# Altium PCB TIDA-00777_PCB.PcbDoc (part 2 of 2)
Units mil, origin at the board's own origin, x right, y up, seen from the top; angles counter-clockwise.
Board outline 1968.5 x 2165.35 mil, 4 copper layers (Top Layer, GND, +2.5V, Bottom Layer), stack 30.48 mil thick; 147 components, 52 nets, 290 pads, 85 vias.
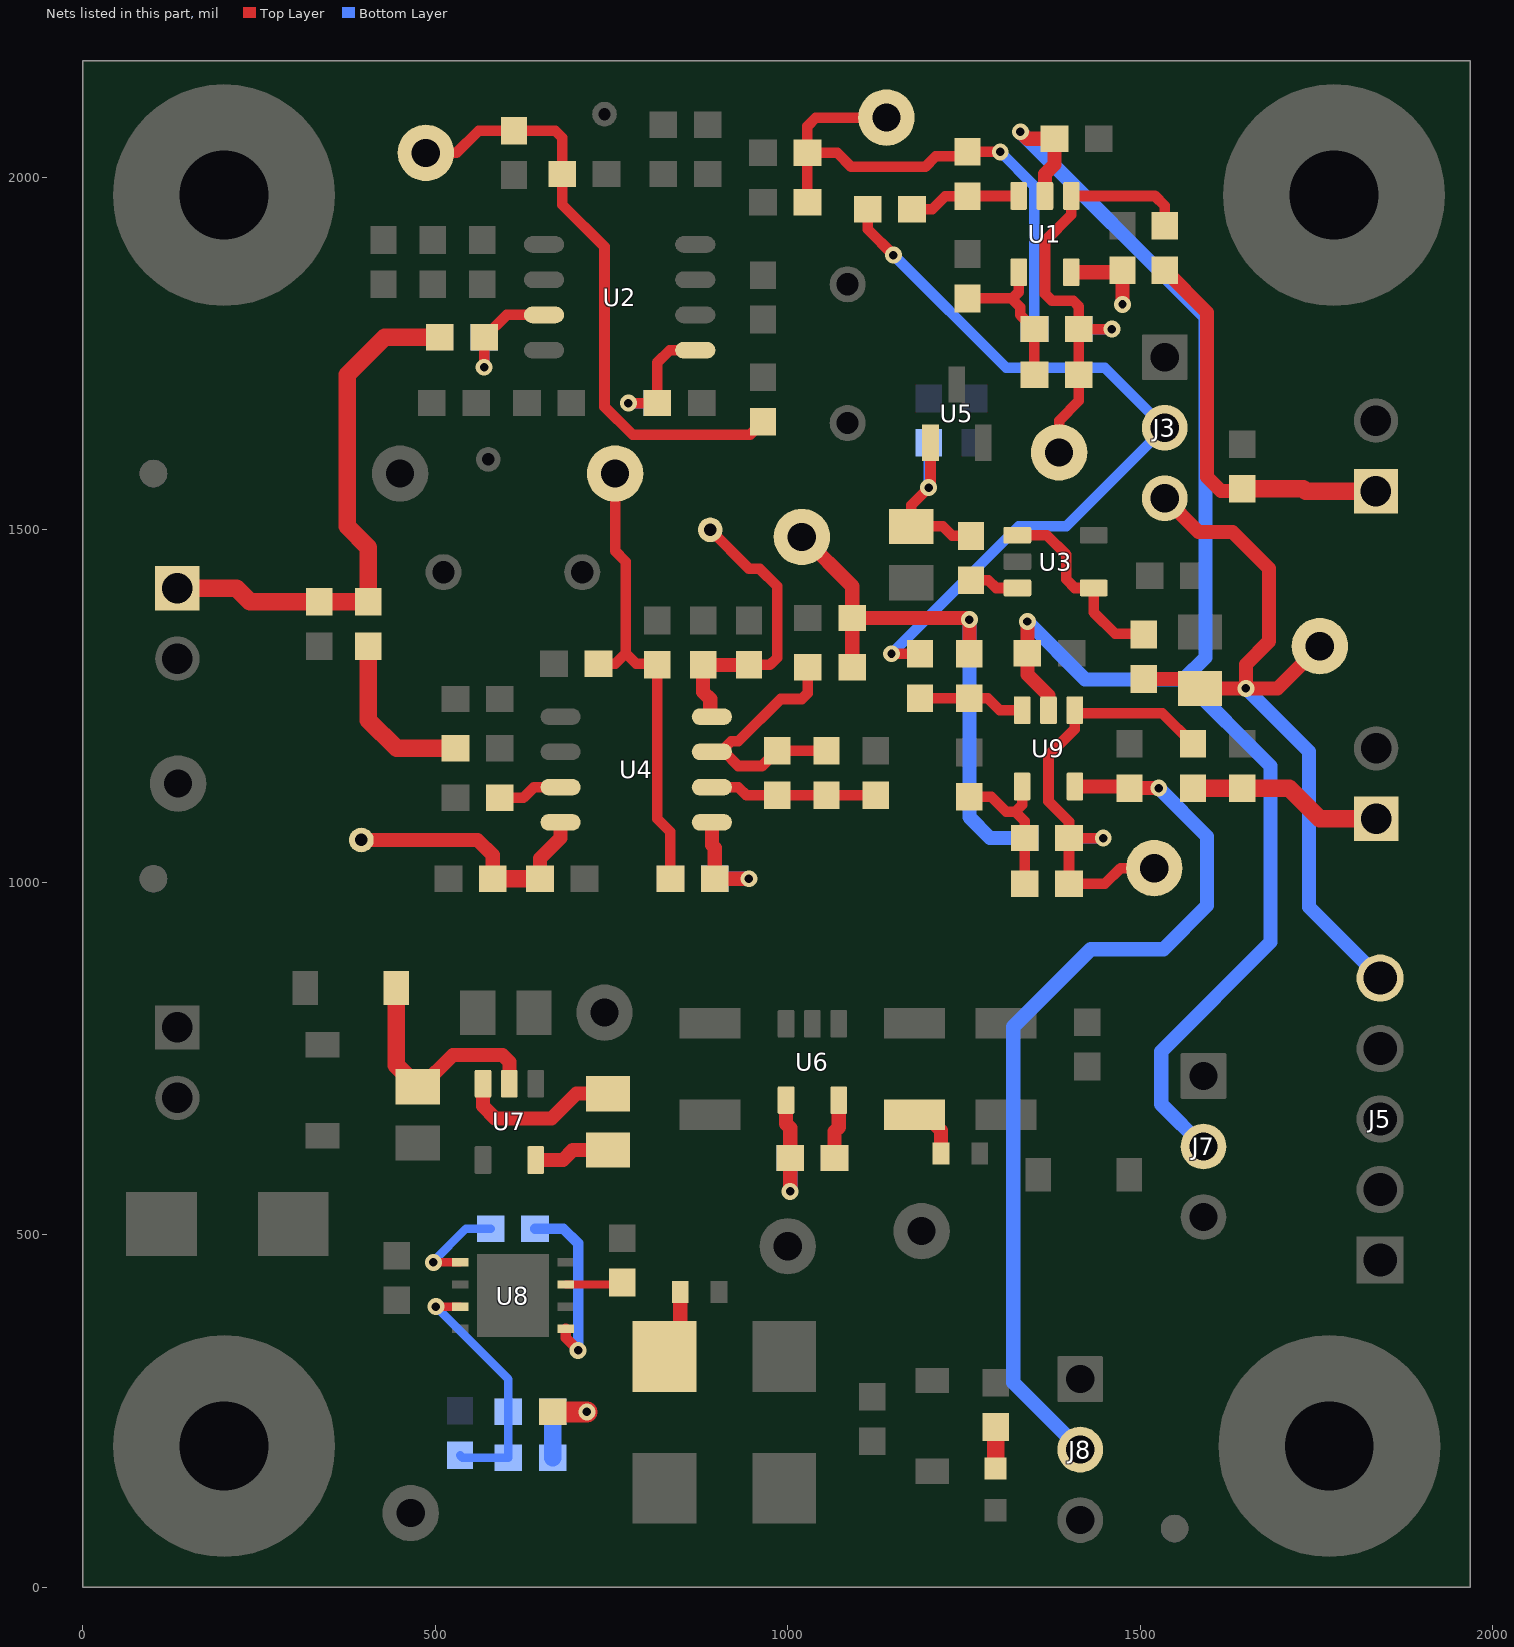
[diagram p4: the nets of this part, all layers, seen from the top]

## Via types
v1: diameter 24, hole 12, Top Layer to Bottom Layer, tented both sides, 79 vias
v2: diameter 19.68, hole 7.87, Top Layer to Bottom Layer, 5 vias
v3: diameter 40, hole 20, Top Layer to Bottom Layer, tented both sides, 1 vias

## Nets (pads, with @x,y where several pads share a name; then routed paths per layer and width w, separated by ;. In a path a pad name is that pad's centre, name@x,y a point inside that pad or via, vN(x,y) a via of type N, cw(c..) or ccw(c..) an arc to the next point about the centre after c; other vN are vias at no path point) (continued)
NetC13_2: C13.2 R47.2 TP17.1 U4.8 | length 433.9
  Top Layer w15: TP17.1@890,1500 945,1445 960,1445 985,1420 985,1318.73 974.77,1308.5 R47.2@945,1308.5
  Top Layer w20: U4.8@909,1235 U4.8@892.28,1235 890,1237.28 890,1260 880,1270 C13.2@880,1308.5 R47.2@945,1308.5
NetC14_1: C14.1 R20.1 R25.2 U4.6 | length 237.5
  Top Layer w15: U4.6@892.28,1135 930,1135 941.5,1123.5 R20.1@985,1123.5 C14.1@1055,1123.5 R25.2@1125,1123.5
NetC14_2: C14.2 R20.2 R54.1 U4.7 | length 374.5
  Top Layer w15: U4.7@892.28,1185 U4.7@905,1185 ; R54.1@1028.5,1305 1028.5,1268.5 1020,1260 990,1260 930,1200 920,1200 U4.7@905,1185 ; C14.2@1055,1186.5 R20.2@985,1186.5 963.5,1165 930,1165 910,1185 U4.7@905,1185
NetC15_1: C15.1 R22.1 R36.2 U5.1 | length 284.2
  Top Layer w15: U5.1@1202.6,1623.66 1202.6,1562.6 v1(1200,1560) 1175,1535 C15.1@1175,1505 1220,1505 1233.5,1491.5 R22.1@1260,1491.5
  Bottom Layer w15: v1(1200,1560) R36.2@1200,1623.5
NetC16_2: C16.2 R53.2 TP18.1 U4.4 | length 388
  Top Layer w20: TP18.1@395,1060 560,1060 581.5,1038.5 R53.2@581.5,1005 ; C16.2@648.5,1005 648.5,1033.5 677.72,1062.72 U4.4@677.72,1085
  Top Layer w25: R53.2@581.5,1005 C16.2@648.5,1005
NetC20_1: C20.1 L1.1 R29.2 U6.5 | length 173.9
  Top Layer w20: R29.2@1066.5,608.7 1066.5,646.5 1072.4,652.4 U6.5@1072.4,690.87 ; C20.1@1189.96,670.04 C20.1@1180,670.04 1194.96,670.04 1217.44,647.56 L1.1@1217.44,615
NetC22_1: C22.1 D3.1 U7.2 | length 336.3
  Top Layer w20: C22.1@475,710 480,710 525,755 595,755 605,745 U7.2@605,714.13
  Top Layer w25: D3.1@444.47,850 444.47,740.53 C22.1@475,710
NetC23_1: C23.1 U7.3 | length 230.8
  Top Layer w20: U7.3@567.6,714.13 567.6,682.4 585,665 665,665 700,700 C23.1@745,700
NetC23_2: C23.2 U7.5 | length 108.5
  Top Layer w20: U7.5@642.4,605.87 680.87,605.87 695,620 C23.2@745,620
NetC26_1: C26.1 C29.1 C31.1 L2.1 R39.2 R41.2 U8.1 | length 522.1
  Top Layer w15: U8.1@684.8,366.26 684.8,353.46 v1(702.52,335.75)
  Top Layer w20: C26.1@825,327.01 847.44,349.45 L2.1@847.44,418.5
  Top Layer w30: C29.1@666.5,248.5 v1(715,248.5)
  Bottom Layer w15: R39.2@641.5,508.5 681.5,508.5 702.52,487.48 v1(702.52,335.75)
  Bottom Layer w25: R41.2@666.5,183.5 C31.1@666.5,248.5 v1(715,248.5)
NetC31_2: C31.2 R40.2 R41.1 U8.7 | length 361.2
  Top Layer w12: v1(500.75,397.76) U8.7@535.2,397.76
  Bottom Layer w12: v1(500.75,397.76) 603.5,295 C31.2@603.5,248.5 R41.1@603.5,183.5 538.5,183.5 R40.2@535,187.01
NetC32_1: C32.1 R7.2 R12.1 U1.4 | length 226.3
  Top Layer w15: R7.2@1255,1828.5 1317.5,1828.5 ; U1.4@1327.6,1865.55 1327.6,1837.6 1318.5,1828.5 1317.5,1828.5 ; C32.1@1350,1720 R12.1@1350,1785 1330,1805 1330,1816 1317.5,1828.5
NetC32_2: C32.2 R12.2 R14.1 R33.2 TP3.1 U1.1 | length 689.2
  Top Layer w15: TP3.1@1385,1610 1385,1655 1412.99,1682.99 C32.2@1412.99,1720 R12.2@1412.99,1785 ; v1(1460,1785) R12.2@1412.99,1785 ; R14.1@1535,1931.5 1535,1960 1521.18,1973.82 U1.1@1402.4,1973.82 1402.4,1947.4 1365,1910 1365,1835 1375,1825 1405,1825 1412.99,1817.01 R12.2@1412.99,1785
  Bottom Layer w15: R33.2@1412.99,1785 v1(1460,1785)
NetC33_2: C33.2 J1.1 R14.2 | length 569.2
  Top Layer w20: R14.2@1535,1868.5 1595,1808.5 1595,1575 1615,1555 1641.5,1555 C33.2@1645,1558.5
  Top Layer w25: C33.2@1645,1558.5 1731.5,1558.5 1735,1555 J1.1@1834.65,1555
NetC34_1: C34.1 R45.2 R46.1 U9.4 | length 221.6
  Top Layer w15: R45.2@1257.64,1121.26 1288.74,1121.26 1310,1100 1322.6,1100 ; U9.4@1332.6,1135.87 1332.6,1110 1322.6,1100 ; C34.1@1336.14,997.76 R46.1@1336.14,1062.76 1336.14,1086.46 1322.6,1100
NetC34_2: C34.2 R26.1 R46.2 R49.2 TP14.1 U9.1 | length 709.8
  Top Layer w15: v1(1447.76,1062.76) R46.2@1399.13,1062.76 ; TP14.1@1520,1020 TP14.1@1505,1020 ; TP14.1@1520,1035 TP14.1@1505,1020 ; R26.1@1575,1196.5 1531.5,1240 1411.54,1240 U9.1@1407.4,1244.13 1407.4,1217.4 1370,1180 1370,1115 1399.13,1085.87 R46.2@1399.13,1062.76 ; R46.2@1399.13,1062.76 C34.2@1399.13,997.76 1450,997.76 1472.24,1020 TP14.1@1505,1020
  Bottom Layer w15: R49.2@1399.13,1062.82 1399.2,1062.76 v1(1447.76,1062.76)
NetC36_2: C36.2 J4.1 R26.2 | length 278
  Top Layer w25: R26.2@1575,1133.5 C36.2@1645,1133.5 1711.5,1133.5 1755,1090 J4.1@1835,1090
NetD5_1: D5.1 R31.1 | length 59
  Top Layer w25: D5.1@1295,168.03 R31.1@1295,227.01
NetJ2_1: J2.1 R9.1 R16.2 R17.2 | length 766.9
  Top Layer w25: J2.1@133.86,1417.24 217.76,1417.24 237.01,1397.99 R16.2@335,1397.99 R17.2@405,1397.99 405,1475 375,1505 375,1720 428.23,1773.23 R9.1@506.3,1773.23
NetR1_2: R1.2 R4.2 U1.3 | length 158.9
  Top Layer w15: R4.2@1176.5,1955 1205,1955 1223.5,1973.5 R1.2@1255,1973.5 1255.31,1973.82 U1.3@1327.6,1973.82
NetR9_2: R9.2 R32.2 U2.3 | length 182.9
  Top Layer w15: v1(569.29,1730.8) R9.2@569.29,1773.23 601.06,1805 U2.3@654.21,1805
  Bottom Layer w15: v1(569.29,1730.8) R32.2@569.29,1773.23
NetR13_2: R13.2 R34.1 U2.5 | length 200.5
  Top Layer w15: v1(774,1680) R13.2@815,1680 815,1737.5 832.5,1755 U2.5@868.78,1755
  Bottom Layer w15: v1(774,1680) R34.1@815,1680
NetR15_1: R15.1 U3.1 U3.4 | length 278.3
  Top Layer w15: U3.1@1325.87,1492.4 1367.6,1492.4 1395,1465 1395,1430 1407.4,1417.6 U3.4@1434.13,1417.6 1434.13,1382.87 1464.63,1352.37 1504.12,1352.37 R15.1@1505,1351.5
NetR17_1: R17.1 R21.1 | length 245.1
  Top Layer w25: R17.1@405,1335 405,1230 445,1190 R21.1@528.5,1190
NetR22_2: R22.2 U3.3 | length 70.4
  Top Layer w15: R22.2@1260,1428.5 1284.76,1428.5 1295.67,1417.6 U3.3@1325.87,1417.6
NetR24_2: R24.2 U4.3 | length 92.4
  Top Layer w15: R24.2@591.5,1120 625,1120 640,1135 U4.3@677.72,1135
NetR27_2: R27.2 R37.2 U4.5 | length 178.8
  Top Layer w20: U4.5@892.28,1085 892.28,1052.72 896.5,1048.5 R27.2@896.5,1005 v1(945,1005)
  Bottom Layer w20: R37.2@896.5,1005 v1(945,1005)
NetR29_1: R29.1 R38.2 U6.4 | length 179
  Top Layer w20: U6.4@997.6,690.87 997.6,657.4 1003.5,651.5 R29.1@1003.5,608.7 v1(1003.5,561.5)
  Bottom Layer w20: v1(1003.5,561.5) R38.2@1003.5,608.7
NetR30_2: R30.2 U8.3 | length 80.5
  Top Layer w12: U8.3@684.8,429.25 764.25,429.25 R30.2@765,428.5
NetR39_1: R39.1 U8.5 | length 139.9
  Top Layer w12: v1(497.24,460.75) U8.5@535.2,460.75
  Bottom Layer w12: v1(497.24,460.75) 497.24,462.24 543.5,508.5 R39.1@578.5,508.5
NetR50_2: R50.2 R51.2 U9.3 | length 152.1
  Top Layer w15: R51.2@1187.64,1261.26 R50.2@1257.64,1261.26 1283.74,1261.26 1300.87,1244.13 U9.3@1332.6,1244.13
REF_2.5V: C9.1 J3.3 J5.5 R15.2 TP4.1 | length 1143.4
  Top Layer w20: R15.2@1505,1288.5 1571.5,1288.5 C9.1@1585,1275 v1(1650,1275) ; J3.3@1535,1545 1583,1497 1631,1497 1683,1445 1683,1342 1650,1309 v1(1650,1275) ; TP4.1@1755,1335 1695,1275 v1(1650,1275)
  Bottom Layer w20: v1(1650,1275) 1739.61,1185.39 1739.61,965 J5.5@1840.55,864.06
V+: C5.2 C35.2 J8.2 U1.5 U9.5 | length 1427.9
  Top Layer w20: U1.5@1402.4,1865.55 C5.2@1475,1865.55 ; U9.5@1407.4,1135.87 1482.64,1135.87 C35.2@1485,1133.5 v1(1526.5,1133.5) ; v1(1475,1820) C5.2@1475,1865.55 ; C5.2@1475,1868.5 C5.2@1475,1865.55 ; C5.2@1480,1868.5 1477.05,1865.55 C5.2@1475,1865.55
  Bottom Layer w20: J8.2@1415,195 1320,290 1320,795 1430,905 1533,905 1595,967 1595,1065 v1(1526.5,1133.5)
V-: C3.2 C37.2 J7.2 U1.2 U9.2 | length 2235.5
  Top Layer w20: v1(1330,2065) 1340,2055 C3.2@1378.5,2055 1378.5,2018.5 1365,2005 U1.2@1365,1973.82 ; v1(1340,1370) C37.2@1340,1325 1340,1295 1370,1265 U9.2@1370,1244.13
  Bottom Layer w20: v1(1330,2065) 1593,1802 1593,1319 1562,1288 ; v1(1340,1370) 1422,1288 1562,1288 ; J7.2@1590,625 1530,685 1530,760 1685,915 1685,1165 1562,1288
V_REF: J3.2 R4.1 R51.1 | length 1127.6
  Top Layer w15: R4.1@1113.5,1955 1113.5,1926.5 v1(1150,1890) ; v1(1147.24,1324.25) R51.1@1187.64,1324.25
  Bottom Layer w15: v1(1147.24,1324.25) 1327.99,1505 1395,1505 J3.2@1535,1645 1450,1730 1310,1730 v1(1150,1890)
VM_GAIN: C4.1 R2.2 R11.1 TP2.1 | length 866.3
  Top Layer w15: TP2.1@486.5,2035 530,2035 561.5,2066.5 R2.2@611.5,2066.5 670,2066.5 680,2056.5 C4.1@680,2005 680,1961.5 740,1901.5 740,1675 780,1635 946.5,1635 R11.1@965,1653.5
VM_INTEGRATOR: C2.1 R1.1 R3.2 R33.1 TP1.1 | length 787.3
  Top Layer w15: R3.2@1027.99,1965 C2.1@1027.99,2035 ; TP1.1@1140,2085 1040,2085 1027.99,2072.99 C2.1@1027.99,2035 ; v1(1301.5,2036.5) R1.1@1255,2036.5 1248.5,2030 1210,2030 1195,2015 1090,2015 1070,2035 C2.1@1027.99,2035
  Bottom Layer w15: v1(1301.5,2036.5) 1350,1987.99 R33.1@1350,1785
VP_GAIN: C38.1 R49.1 R50.1 R54.2 TP7.1 | length 800.5
  Top Layer w20: TP7.1@1021.5,1490 1091.5,1420 C38.1@1091.5,1375 ; R54.2@1091.5,1305 C38.1@1091.5,1375 ; R50.1@1257.64,1324.25 v1(1257.64,1372.64) 1255.28,1375 C38.1@1091.5,1375
  Bottom Layer w20: v1(1257.64,1372.64) 1257.64,1092.36 1287.18,1062.82 R49.1@1336.14,1062.82
VP_INTEGRATOR: C12.1 R18.2 R27.1 TP6.1 | length 668.9
  Top Layer w15: R18.2@731.5,1310 755,1310 770,1325 ; TP6.1@755,1580 755,1470 770,1455 770,1325 ; R27.1@833.5,1005 833.5,1071.5 815,1090 C12.1@815,1308.5 813.5,1310 785,1310 770,1325
pads on no net: FID1.1 FID2.1 FID3.1 FID4.1 FID5.1 FID6.1 H1.1 H2.1 H3.1 H4.1 H5.0 H6.0 H7.0 H8.0 U5.3 U8.2 U8.6

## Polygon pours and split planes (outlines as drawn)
-VE_UNREG on Top Layer "TOP_LAYER_-VE_UNREG_P024" (solid, remove dead copper, pour order 24): 835,815 840,820 1034,820 1045,809 1045,790.55 1034.45,780 840,780 835,785
GND on Top Layer "TOP_LAYER_GND_P014" (solid, remove dead copper, pour order 14): 1065,850 1065,785 1070,780 1360,780 1365,785 1460,785 1470,795 1470,860 1460,870 1085,870
-2.5V on Top Layer "TOP_LAYER_-2.5V_P012" (solid, remove dead copper, pour order 12): 1265,680 1275,690 1340,690 1405,755 1450,755 1460,745 1460,700 1450,690 1405,690 1360,645 1270,645 1265,650
NetC20_1 on Top Layer "TOP_LAYER_NETC20_1_P010" (solid, remove dead copper, pour order 10): 1045,705 1050,710 1110,710 1130,690 1220,690 1225,685 1225,650 1220,645 1135,645 1130,640 1130,600 1120,590 1050,590 1045,595
+2.5V on Top Layer "TOP_LAYER_+2.5V_P004" (solid, remove dead copper, pour order 4): 940,293.5 955,278.5 1040,278.5 1075,243.5 1130,243.5 1155,243.5 1220,243.5 1225,248.5 1225,333.5 1215,343.5 1110,343.5 1045,408.5 955,408.5 940,393.5
GND on Top Layer "TOP_LAYER_GND_P000" (solid, remove dead copper, pour order 0): 470,453.5 470,478.5 475,483.5 553.73,483.5 560,477.24 560,73.5 590,43.5 1185,43.5 1225,83.5 1225,173.5 1220,178.5 1185,178.5 1140,223.5 1100,223.5 1055,178.5 635,178.5 620,193.5 620,308.5 660,348.5 660,458.5 690,458.5 695,463.5 695,518.5 685,528.5 425,528.5 410,513.5 410,453.5 415,448.5 465,448.5
NetC26_1 on Top Layer "TOP_LAYER_NETC26_1_P020" (solid, remove dead copper, pour order 20): 675,373.5 675,333.5 645,303.5 645,233.5 645,228.5 650,223.5 655,218.5 721.1,218.5 725,218.5 740,233.5 740,253.5 740,263.5 760,283.5 855,283.5 865,293.5 865,358.5 850,373.5 695,373.5
+5V on Top Layer "TOP_LAYER_+5V_P022" (solid, remove dead copper, pour order 22): 420,423.5 425,428.5 455,428.5 461.42,422.09 461.42,389.31 477.22,373.5 505,373.5 540,373.5 545,368.5 545,323.5 540,318.5 500,318.5 456.5,318.5 415,360 415,418.5
GND on GND "GND_GND_P016" (solid, remove dead copper, pour order 16): 475,2125 1525,2125 1550,2100 1550,1850 1625,1775 1875,1775 1925,1725 1925,450 1900,425 1625,425 1525,325 1525,75 1500,50 1375,50 475,50 450,75 450,300 325,425 75,425 50,450 50,1700 100,1750 350,1750 425,1825 425,2075
+2.5V on +2.5V "+2.5V_+2.5V_P018" (solid, remove dead copper, pour order 18): 450,1700 450,1859.53 450,2100 575,2100 1100,2100 1100,1065.36 1150,1015.36 1150,450 1100,400 725,400 175,950 125,950 100,975 100,1650 150,1700
V+ on +2.5V "+2.5V_V+_P028" (solid, remove dead copper, pour order 28): 1125,1825 1125,1075 1225,975 1575,975 1675,975 1700,1000 1700,1150 1700,1475 1700,1650 1700,1700 1600,1800 1550,1850 1150,1850

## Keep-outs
Keep-Out Layer:
  lines w10: 25,400 275,400 400,275 400,25 ; 25,1778.15 313.15,1778.15 380,1845 380,2120.35 380,2140.35 ; 1550,25 1550,300 1635,385 1943.5,385 ; 1575,2140.35 1575,1903.15 1675,1803.15 1943.5,1803.15 ; 25,25 1943.5,25 1943.5,2140.35 25,2140.35 25,25
  text ".Layer_Name" at 577,-858.49 h60

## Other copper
Top Layer:
  text ".Layer_Name" at 577,-858.49 h60
GND:
  text "GND" at 577,-858.49 h60
+2.5V:
  text "+2.5V" at 577,-858.49 h60
Bottom Layer:
  text ".Layer_Name" at 577,-858.49 h60

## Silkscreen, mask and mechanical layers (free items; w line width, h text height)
Top Overlay:
  circle w10: c1325,1540 r8.54
  circle w10: c638,1263 r7.07
  circle w10: c617.5,1938 r6.4
  circle w10: c1401,2012 r6.71
  circle w10: c1073,843 r7.21
  circle w10: c642,754 r6.4
  lines w6: 150,1750 265,1750 ; 455,960 615,960 620.02,965.02 620.02,977.73 ; 635,1350 765,1350 775,1340 785,1340 ; 915,1940 915,1977.72 914.98,1977.73 ; 1145,1065 1145,1070 1165,1090 1165,1095 1165,1225 ; 1180,1080 1180,1210 1190,1220 1217.66,1220 1230.44,1232.77 ; 1510,1379.98 1510,1390 1520,1400 1635,1400 ; 1560,975 1570,965 1710,965 ; 1690,1080 1585,1080 ; 265,1750 260,1755 260,1745 265,1750 ; 1585,1080 1595,1090 1595,1070 1585,1080 ; 100,1655 100,1745 100,1760 110,1770 325,1770 390,1835 390,1945 405,1960 585,1960 605,1940 605,1820 595,1810 400,1810 340,1750 340,1685 295,1640 115,1640 100,1655
  lines w45: 100,925 1875,925
  text "K" at 495,825 h50
  text "K" at 370,550 h50
  text "K" at 1275,545 h50
  text "K" at 1195,345 h50
  text "K" at 1325,90 h50
  text ".Layer_Name" at 577,-858.49 h60
Bottom Overlay:
  text "'.PRJ_Number'.PCB_Rev" at 1015,1270 h108.27
  text ".Layer_Name" at 577,-858.49 h60
Top Paste:
  text ".Layer_Name" at 577,-858.49 h60
Bottom Paste:
  text ".Layer_Name" at 577,-858.49 h60
Top Solder:
  text ".Layer_Name" at 577,-858.49 h60
  text ".Layer_Name" at 577,-858.49 h60
Bottom Solder:
  text ".Layer_Name" at 577,-858.49 h60
Drill Guide:
  text ".Layer_Name" at 577,-858.49 h60
M1 Board Outline:
  the board outline again, w10
M2 Board Dimensions:
  rectangle: 125,-400 500,-275
  rectangle: 0,-275 125,-150
  lines w7: 0,-275 1000,-275 ; 0,-150 0,-400 1000,-400 1000,-150 ; 125,-400 125,-150 ; 250,-400 250,-150 ; 500,-400 500,-150 ; 750,-400 750,-150
M3 3D STEP Top:
  text ".Layer_Name" at 577,-858.49 h60
M4 3D STEP Bottom:
  text ".Layer_Name" at 577,-858.49 h60
M5 Assembly Top:
  circle w10: c1208.92,1579 r4.24
  circle w10: c1405,1270 r6.71
  circle w10: c1858,470 r8.06
  circle w10: c725,335 r7.81
  circle w10: c1070,830 r7.07
  circle w10: c642.4,745 r6.32
  circle w10: c1305,1495 r6.71
  circle w10: c1405,2000 r6.71
  lines w8: 517.48,344.61 517.48,326.89 541.1,326.89 ; 517.48,482.4 517.48,500.12 541.1,500.12 ; 678.9,326.89 702.52,326.89 702.52,344.61 ; 678.9,500.12 702.52,500.12 702.52,482.4 ; 1180.94,1665 1180.94,1692.56 1212.44,1692.56 ; 1267.56,1692.56 1299.06,1692.56 1299.06,1665
  lines w10: -292,-930.17 6308,-930.17 ; -292,-726.83 6310,-726.83 ; -292,-523.5 -292,-1133.5 3713,-1133.5 6310,-1133.5 6310,-523.5 -291.5,-523.5 -291.5,-1133.5 1284,-1133.5 ; 2173,-1133.5 2173,-523.5 ; 3440,-726.83 3440,-523.5 ; 4280,-726.83 4280,-523.5 ; 4902,-1140 4902,-937.17
  text "COMPONENTS MARKED 'DNP' SHOULD NOT BE POPULATED." at 1153.5,-318.5 h60
  text "ASSEMBLY VARIANT:" at 1153,-434 h60
  text ".VariantName" at 2189,-434 h60
  text "PCB VIEWED FROM TOP SIDE" at -228.5,-655.67 h60
  text "BOARD #:" at 2248,-655.67 h60
  text ".PRJ_Number" at 2793.5,-655.67 h60
  text "REV:" at 3638,-655.67 h60
  text ".PCB_Rev" at 3929.5,-655.67 h60
  text "SVN REV:" at 4476,-655.67 h60
  text ".VersionControl_RevNumber" at 4982,-655.67 h60
  text ".Layer_Name" at 577,-858.49 h60
  text "TID #:" at 2248,-859 h60
  text ".TID" at 2793.5,-859 h60
  text "PLOT NAME =" at -228.5,-1064.34 h60
  text ".plot_File_Name" at 577,-1064.34 h60
  text "GENERATED    :" at 2250,-1064.34 h60
  text ".Print_Date" at 3119.5,-1064.34 h60
  text ".Print_Time" at 3848.5,-1064.34 h60
  text "TEXAS INSTRUMENTS" at 5113,-1064.34 h60
M6 Assembly Bottom:
  lines w10: -292.5,-727.33 6309.5,-727.33 ; -290.5,-930.67 6309.5,-930.67 ; 1115.5,-1140.5 1115.5,-937.67 ; 1737.5,-727.33 1737.5,-524 ; 2577.5,-727.33 2577.5,-524 ; 3844.5,-1134 3844.5,-524 ; 4733.5,-1134 6309,-1134 6309,-524 -292.5,-524 -292.5,-1134 2304.5,-1134 6309.5,-1134 6309.5,-524
  text "COMPONENTS MARKED 'DNP' SHOULD NOT BE POPULATED." at 6102,-318 h60
  text ".VariantName" at 5058,-434 h60
  text "ASSEMBLY VARIANT:" at 6097,-434 h60
  text ".VersionControl_RevNumber" at 1035.5,-656.17 h60
  text "SVN REV:" at 1541.5,-656.17 h60
  text ".PCB_Rev" at 2088,-656.17 h60
  text "REV:" at 2379.5,-656.17 h60
  text ".PRJ_Number" at 3224,-656.17 h60
  text "BOARD #:" at 3769.5,-656.17 h60
  text "PCB VIEWED FROM BOTTOM SIDE" at 6246,-656.17 h60
  text ".Layer_Name" at 5670,-855 h60
  text ".TID" at 3224,-859.5 h60
  text "TID #:" at 3769.5,-859.5 h60
  text "TEXAS INSTRUMENTS" at 904.5,-1064.84 h60
  text ".Print_Time" at 2169,-1064.84 h60
  text ".Print_Date" at 2898,-1064.84 h60
  text "GENERATED    :" at 3767.5,-1064.84 h60
  text ".plot_File_Name" at 5440.5,-1064.84 h60
  text "PLOT NAME =" at 6246,-1064.84 h60
M9 Title Sheet:
  drawing of 57 lines, arcs and shapes, not listed
  text "1" at 739.84,8036.5 h70
  text "2" at 3235.5,8036.5 h70
  text "3" at 5724.84,8036.5 h70
  text "4" at 8231.51,8036.5 h70
  text "5" at 10730.5,8036.5 h70
  text "6" at 13235.5,8036.5 h70
  text "A" at -416.5,6893.5 h70
  text "A" at 14383.5,6893.5 h70
  text "B" at -416.5,4513.5 h70
  text "B" at 14383.5,4513.5 h70
  text "C" at -416.5,2138.5 h70
  text "C" at 14383.5,2138.5 h70
  text "PROJECT TITLE:" at 11343.5,277.5 h45
  text ".PRJ_Title" at 11393.5,144.17 h70
  text "DESIGNED FOR:" at 11343.5,-23.5 h45
  text ".PRJ_Customer" at 11393.5,-163.5 h70
  text "D" at -416.5,-231.5 h70
  text "D" at 14383.5,-231.5 h70
  text "FILE NAME:" at 11343.5,-323.5 h45
  text ".PCB_File_Name_No_Path" at 11393.5,-443.5 h70
  text "Texas Instruments (TI) and/or its licensors do not warrant the accuracy or completeness of this specification" at 6374,-605.34 h45
  text "ENGINEER:" at 11343.5,-613.5 h45
  text "LAYOUT BY:" at 12848.5,-613.5 h45
  text "or any information contained therein. TI and/or its licensors do not warrant that this design will meet" at 6329.01,-718 h45
  text ".PRJ_Engineer" at 11393.5,-768.49 h70
  text ".PCB_Layout" at 12899,-768.49 h70
  text "the specifications, will be suitable for your application or fit for any particular purpose, or will operate in" at 6329.01,-830.67 h45
  text "ALTIUM DESIGNER VERSION:" at 12848.5,-923.5 h45
  text "an implementation. TI and/or its licensors do not warrant that the design is production worthy. You should" at 6329.01,-943.33 h45
  text "completely validate and test your design implementation to confirm the system functionality for your application." at 6374,-1056 h45
  text ".print_Scale" at 11393.5,-1056.83 h70
  text ".Application_BuildNumber" at 12899,-1056.83 h70
  text "1" at 739.84,-1263.5 h70
  text "2" at 3235.5,-1263.5 h70
  text "3" at 5724.84,-1263.5 h70
  text "4" at 8231.51,-1263.5 h70
  text "5" at 10730.5,-1263.5 h70
  text "6" at 13235.5,-1263.5 h70
M10 Fab Notes:
  drawing of 185 lines, arcs and shapes, not listed
  text "DESIGN INFORMATION" at 12378.02,6201 h60
  text "MIL" at 13035,6030 h60
  text "MIN. TRACK WIDTH:" at 11733.46,6021 h60
  text "12" at 12800,6020 h60
  text "8" at 12830,5896 h60
  text "MIL" at 13035,5895 h60
  text "MIN. CLEARANCE:" at 11733.46,5889 h60
  text "MIN. VIA PAD SIZE:" at 11733.46,5757 h60
  text "19.685" at 12665,5755 h60
  text "MIL" at 13040,5755 h60
  text "0.15mm (5.9MIL)" at 12428.46,5615.29 h60
  text "MINIMUM ANNULAR RING" at 11404.23,5611 h60
  text "EXTERNAL" at 13136.46,5611 h60
  text "PER" at 11604.23,5493 h60
  text "IPC-D-275 CLASS 2 LEVEL C" at 11824.23,5493 h60
  text "MIL, HOLES" at 13312.46,5380.71 h60
  text "+/-" at 12920,5380 h60
  text "+/-" at 13774,5380 h60
  text "REGISTRATION TOLERANCES:" at 11404.23,5375 h60
  text "METAL" at 12604,5375 h60
  text "5" at 13180.2,5375 h60
  text "3" at 14013.2,5375 h60
  text "MIL" at 14129.46,5375 h60
  text "+/-" at 13774,5262 h60
  text "HOLE SIZE TOLERANCE (UNLESS OTHERWISE SPECIFIED):" at 11404.23,5257 h60
  text "3" at 14013.2,5257 h60
  text "MIL" at 14129.46,5257 h60
  text "MATERIAL:" at 11329.46,5047.54 h60
  text "FR-4 High Tg" at 12315.9,4907.21 h60
  text "FR-408" at 11750.46,4898.64 h60
  text "OTHER" at 13238.46,4898.64 h60
  text "X" at 12161,4895 h60
  text "63 MIL (1.6mm) +/-10%" at 12070.56,4735.92 h60
  text "THICKNESS:" at 11404.23,4731.64 h60
  text "X" at 11942.4,4731.64 h60
  text "OTHER" at 13355.46,4731.64 h60
  text "TOLERANCE:" at 11404.23,4573.64 h60
  text "X" at 12243.53,4573.64 h60
  text "ANSI IPC-6012 TYPE 3 CLASS 2" at 12430.48,4573.64 h60
  text "OTHER +/-" at 12430.46,4417.64 h60
  text "BOW & TWIST:" at 11404.23,4260.64 h60
  text "X" at 12243.53,4260.64 h60
  text "ANSI IPC-6012 TYPE 3 CLASS 2" at 12430.48,4260.64 h60
  text "OTHER +/-" at 12430.46,4102.13 h60
  text "DRILLING:" at 11329.46,3963.64 h60
  text "REFERENCE:" at 11404.23,3846.64 h60
  text "X" at 12052.46,3846.64 h60
  text "AS SHOWN" at 12239.46,3846.64 h60
  text "X" at 12953.46,3846.64 h60
  text "NC_DRILL FILES" at 13090.46,3846.64 h60
  text "PTH COPPER THICKNESS:" at 11404.23,3688.64 h60
  text "X" at 12534.46,3688.64 h60
  text "20-30 um" at 12671.46,3688.64 h60
  text "OTHER" at 13388.46,3688.64 h60
  text "BOARD FINISH:" at 11329.46,3529.64 h60
  text "X" at 12943.46,3416.64 h60
  text "SILKSCREEN:" at 11484.68,3411.64 h60
  text "X" at 12433.46,3411.64 h60
  text "TOP" at 12559.46,3411.64 h60
  text "BOTTOM" at 13070.46,3411.64 h60
  text "SILKSCREEN COLOR:" at 11484.68,3244.64 h60
  text "X" at 12432.42,3244.64 h60
  text "WHITE" at 12559.46,3244.64 h60
  text "OTHER" at 13070.46,3244.64 h60
  text "X" at 12563.42,3085.44 h60
  text "GREEN" at 12690.46,3085.44 h60
  text "OTHER" at 13308.46,3085.44 h60
  text "SOLDER RESIST COLOR:" at 11484.68,3074.64 h60
  text "X" at 12563.42,2915.44 h60
  text "MATTE" at 12690.46,2915.44 h60
  text "SEMI-GLOSS" at 13308,2914.8 h60
  text "IMMERSION GOLD (ENIG)" at 12390.46,2726.92 h60
  text "ENEPIG" at 13728,2723.64 h60
  text "SURFACE FINISH:" at 11329.46,2722.64 h60
  text "X" at 12203.51,2722.64 h60
  text "IMM. TIN/SILVER OR EQUIV" at 11659,2565.64 h60
  text "OTHER" at 13090.46,2565.64 h60
  text "ARRAY/PANEL:" at 11329.46,2386.64 h60
  text "CUT AND TRIM PER M1 BOARD OUTLINE" at 12390.46,2382.35 h60
  text "N.C. ROUTE" at 12390.46,2230.64 h60
  text "X" at 13069.46,2230.64 h60
  text "V. SCORE" at 13256.46,2230.64 h60
  text "CERTIFICATION:" at 11329.46,2093.64 h60
  text "MATERIALS AND WORKMANSHIP FOR ALL PCBS" at 12054.46,2093.64 h60
  text "TO MEET OR EXCEED THE REQUIREMENTS OF:" at 12054.46,1995.64 h60
  text "X" at 11680.96,1859.13 h60
  text "ANSI IPC-A-600F CLASS ->" at 11819.96,1859.13 h60
  text "X" at 13459.02,1859.13 h60
  text "2" at 13577.96,1859.14 h60
  text "1" at 13262.96,1857.64 h60
  text "3" at 13931.96,1857.64 h60
  text "X" at 12495.02,1699.64 h60
  text "RoHS" at 12631.96,1699.64 h60
  text "OTHER" at 13276.36,1699.64 h60
  text "PER ORDER" at 13673.42,1699.64 h60
  text "ALL BOARDS MUST MEET OR EXCEED UL94-V0 REQUIREMENTS." at 11357,1534 h60
  text "PCB MUST BEAR THE UL94V-0 UL REGISTERED MATERIAL ID NUMBER" at 11357,1414 h60
  text "IMPEDANCE CONTROL:" at 13335,1305 h60
  text "ADDITIONAL REQUIREMENTS:" at 11329.46,1240.64 h60
  text "VIA TENTED:" at 12460,1240 h60
  text "X" at 13043.02,1209.64 h60
  text "YES" at 13165,1200 h60
  text "X" at 13989.46,1151.64 h60
  text "YES" at 13745,1150 h60
  text "NO" at 14119.5,1150 h60
  text "MICROSECTION:" at 11404.23,1125.64 h60
  text "YES" at 12309.96,1125.64 h60
  text "REQUIRED" at 13171.46,969.49 h60
  text "BARE BOARD ELEC. TEST:" at 11404.23,966.64 h60
  text "NONE" at 12709.96,966.64 h60
  text "X" at 13044.46,966.64 h60
  text "PER ORDER" at 13763.46,966.64 h60
M11 Gerber Information:
  lines w10: -292,-930.17 6308,-930.17 ; -292,-726.83 6310,-726.83 ; -292,-523.5 -292,-1133.5 3713,-1133.5 6310,-1133.5 6310,-523.5 -291.5,-523.5 -291.5,-1133.5 1284,-1133.5 ; 2173,-1133.5 2173,-523.5 ; 3440,-726.83 3440,-523.5 ; 4280,-726.83 4280,-523.5 ; 4902,-1140 4902,-937.17
  text "ALL ARTWORK VIEWED FROM TOP SIDE" at -228.5,-655.67 h60
  text "BOARD #:" at 2248,-655.67 h60
  text ".PRJ_Number" at 2793.5,-655.67 h60
  text "REV:" at 3638,-655.67 h60
  text ".PCB_Rev" at 3929.5,-655.67 h60
  text "SVN REV:" at 4476,-655.67 h60
  text ".VersionControl_RevNumber" at 4982,-655.67 h60
  text "LAYER NAME =" at -228.5,-858.49 h60
  text "TID #:" at 2248,-859 h60
  text ".TID" at 2793.5,-859 h60
  text "PLOT NAME =" at -228.5,-1064.34 h60
  text ".plot_File_Name" at 577,-1064.34 h60
  text "GENERATED    :" at 2250,-1064.34 h60
  text ".Print_Date" at 3119.5,-1064.34 h60
  text ".Print_Time" at 3848.5,-1064.34 h60
  text "TEXAS INSTRUMENTS" at 5113,-1064.34 h60
M12 Stackup:
  drawing of 269 lines, arcs and shapes, not listed
  text "Layer" at 9885.86,7865 h60
  text "Name" at 10295.77,7865 h60
  text "Material" at 11155.54,7865 h60
  text "Thickness" at 12015.3,7865 h60
  text "Constant" at 12665.14,7865 h60
  text "Board Layer Stack" at 13235,7865 h60
  text "1" at 9885.86,7745 h60
  text "Top Overlay" at 10295.77,7745 h60
  text "2" at 9885.86,7625 h60
  text "Top Solder" at 10295.77,7625 h60
  text "Solder Resist" at 11155.54,7625 h60
  text "0.40mil" at 12015.3,7625 h60
  text "3.5" at 12665.14,7625 h60
  text "3" at 9885.86,7505 h60
  text "Top Layer" at 10295.77,7505 h60
  text "Copper" at 11155.54,7505 h60
  text "1.37mil" at 12015.3,7505 h60
  text "4" at 9885.86,7385 h60
  text "Dielectric1" at 10295.77,7385 h60
  text "FR-4 High Tg" at 11155.54,7385 h60
  text "10.00mil" at 12015.3,7385 h60
  text "4.2" at 12665.14,7385 h60
  text "5" at 9885.86,7265 h60
  text "GND" at 10295.77,7265 h60
  text "Copper" at 11155.54,7265 h60
  text "1.37mil" at 12015.3,7265 h60
  text "6" at 9885.86,7145 h60
  text "Dielectric2" at 10295.77,7145 h60
  text "FR-4 High Tg" at 11155.54,7145 h60
  text "5.00mil" at 12015.3,7145 h60
  text "4.2" at 12665.14,7145 h60
  text "7" at 9885.86,7025 h60
  text "+2.5V" at 10295.77,7025 h60
  text "Copper" at 11155.54,7025 h60
  text "1.37mil" at 12015.3,7025 h60
  text "8" at 9885.86,6905 h60
  text "Dielectric3" at 10295.77,6905 h60
  text "FR-4 High Tg" at 11155.54,6905 h60
  text "10.00mil" at 12015.3,6905 h60
  text "4.2" at 12665.14,6905 h60
  text "9" at 9885.86,6785 h60
  text "Bottom Layer" at 10295.77,6785 h60
  text "Copper" at 11155.54,6785 h60
  text "1.37mil" at 12015.3,6785 h60
  text "10" at 9885.86,6665 h60
  text "Bottom Solder" at 10295.77,6665 h60
  text "Solder Resist" at 11155.54,6665 h60
  text "0.40mil" at 12015.3,6665 h60
  text "3.5" at 12665.14,6665 h60
M13 Component Bodies Top:
  text ".Layer_Name" at 577,-858.49 h60
M14 Component Bodies Bottom:
  text ".Layer_Name" at 577,-858.49 h60
M15 Courtyards Top:
  text ".Layer_Name" at 577,-858.49 h60
M16 Courtyards Bottom:
  text ".Layer_Name" at 577,-858.49 h60
Drill Drawing:
  circle w10: c4078.8,1632.16 r16.59
  circle w10: c4078.8,1632.16 r27.66
  circle w10: c4078.8,885.41 r27.66
  lines w10: 4051.14,996.04 4064.97,996.04 4078.8,982.21 4092.63,996.04 4106.46,996.04 4092.63,1009.87 4106.46,1023.7 4092.63,1023.7 4078.8,1037.52 4064.97,1023.7 4051.14,1023.7 4064.97,1009.87 4051.14,996.04 ; 4051.14,1106.67 4078.8,1120.5 4106.46,1106.67 4092.63,1134.33 4106.46,1161.98 4078.8,1148.15 4051.14,1161.98 4064.97,1134.33 4051.14,1106.67 ; 4051.14,1231.13 4106.46,1231.13 4106.46,1286.44 4051.14,1286.44 4051.14,1231.13 ; 4051.14,1410.9 4106.46,1410.9 4078.8,1355.59 4051.14,1410.9 ; 4051.14,1535.36 4106.46,1535.36 4078.8,1480.04 4051.14,1535.36 ; 4051.14,1742.79 4064.97,1742.79 4064.97,1728.96 4092.63,1728.96 4092.63,1742.79 4106.46,1742.79 4106.46,1770.45 4092.63,1770.45 4092.63,1784.28 4064.97,1784.28 4064.97,1770.45 4051.14,1770.45 4051.14,1742.79 ; 4051.14,1853.42 4106.46,1853.42 4106.46,1908.74 4051.14,1908.74 4051.14,1853.42 ; 4062.21,1399.84 4095.39,1399.84 4078.8,1366.65 4062.21,1399.84 ; 4062.21,1864.48 4095.39,1864.48 4095.39,1897.67 4062.21,1897.67 4062.21,1864.48
  lines w12: 4001,820.41 6704.25,820.41 ; 4001,1940.54 6704.25,1940.54 ; 4339.17,695.95 4339.17,2065 ; 4671.28,695.95 4671.28,2065 ; 5308.29,695.95 5308.29,2065 ; 5567.64,695.95 5567.64,2065 ; 5943.06,695.95 5943.06,2065 ; 4001,695.95 6704.25,695.95 6704.25,2065 4001,2065 4001,695.95
  text "Symbol" at 4075.68,1977.88 h72
  text "Quantity" at 4376.51,1977.88 h72
  text "Finished Hole Size" at 4708.62,1977.88 h72
  text "Plated" at 5345.62,1977.88 h72
  text "Hole Type" at 5604.98,1977.88 h72
  text "Drill Layer Pair" at 5980.4,1977.88 h72
  text "5" at 4376.51,1853.42 h60
  text "7.87mil (0.200mm)" at 4708.62,1853.42 h60
  text "PTH" at 5345.62,1853.42 h60
  text "Round" at 5604.98,1853.42 h60
  text "Top Layer - Bottom Layer" at 5980.4,1853.42 h60
  text "79" at 4376.51,1728.96 h60
  text "12.00mil (0.305mm)" at 4708.62,1728.96 h60
  text "PTH" at 5345.62,1728.96 h60
  text "Round" at 5604.98,1728.96 h60
  text "Top Layer - Bottom Layer" at 5980.4,1728.96 h60
  text "4" at 4376.51,1604.5 h60
  text "17.72mil (0.450mm)" at 4708.62,1604.5 h60
  text "PTH" at 5345.62,1604.5 h60
  text "Round" at 5604.98,1604.5 h60
  text "Top Layer - Bottom Layer" at 5980.4,1604.5 h60
  text "1" at 4376.51,1480.04 h60
  text "20.00mil (0.508mm)" at 4708.62,1480.04 h60
  text "PTH" at 5345.62,1480.04 h60
  text "Round" at 5604.98,1480.04 h60
  text "Top Layer - Bottom Layer" at 5980.4,1480.04 h60
  text "4" at 4376.51,1355.59 h60
  text "31.50mil (0.800mm)" at 4708.62,1355.59 h60
  text "PTH" at 5345.62,1355.59 h60
  text "Round" at 5604.98,1355.59 h60
  text "Top Layer - Bottom Layer" at 5980.4,1355.59 h60
  text "22" at 4376.51,1231.13 h60
  text "40.00mil (1.016mm)" at 4708.62,1231.13 h60
  text "PTH" at 5345.62,1231.13 h60
  text "Round" at 5604.98,1231.13 h60
  text "Top Layer - Bottom Layer" at 5980.4,1231.13 h60
  text "8" at 4376.51,1106.67 h60
  text "43.31mil (1.100mm)" at 4708.62,1106.67 h60
  text "PTH" at 5345.62,1106.67 h60
  text "Round" at 5604.98,1106.67 h60
  text "Top Layer - Bottom Layer" at 5980.4,1106.67 h60
  text "5" at 4376.51,982.21 h60
  text "47.24mil (1.200mm)" at 4708.62,982.21 h60
  text "PTH" at 5345.62,982.21 h60
  text "Round" at 5604.98,982.21 h60
  text "Top Layer - Bottom Layer" at 5980.4,982.21 h60
  text "4" at 4376.51,857.75 h60
  text "125.98mil (3.200mm)" at 4708.62,857.75 h60
  text "PTH" at 5345.62,857.75 h60
  text "Round" at 5604.98,857.75 h60
  text "Top Layer - Bottom Layer" at 5980.4,857.75 h60
  text "132 Total" at 4376.51,733.29 h60
  text "DRILL TOLERANCE" at 4000,550 h80
  text "FOR PTH +/- 3MIL" at 4000,465 h80
  text "7.87mil drill:+0/-7.87mil" at 4000,385 h80
  text "12mil drill:+0/-12mil" at 4000,305 h80
  text ".Layer_Name" at 577,-858.49 h60
M17 Embedded Cavity:
  text ".Layer_Name" at 577,-858.49 h60
M18 Embedded Assembly:
  text ".Layer_Name" at 577,-858.49 h60
M19 Embedded Keepout:
  text ".Layer_Name" at 577,-858.49 h60

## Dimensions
0,0 to 1968.5,0 on M2 Board Dimensions
0,0 to 0,2165.35 on M2 Board Dimensions
0,-400 to 1000,-400 on M2 Board Dimensions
